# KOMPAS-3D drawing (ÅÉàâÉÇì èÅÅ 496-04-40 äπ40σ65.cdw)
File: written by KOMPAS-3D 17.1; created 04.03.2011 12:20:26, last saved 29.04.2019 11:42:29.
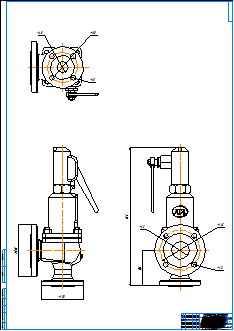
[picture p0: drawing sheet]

Sheet 1: A0, portrait

Title block, sheet 1: name: Прегран Ду 40х65; material: Внимание! Данный продукт является объектом авторского права ООО «Торговый Дом АДЛ». / Запрещается изменение, копирование, распространение / (в том числе путем копирования на другие сайты и ресурсы в Интернете) / или любое иное использование информации и объектов без предварительного / согласия правообладателя (ООО «Торговый Дом АДЛ»).; scale: 1:1; sheets: 1; organisation: ООО "Торговый дом АДЛ"; sheet format: A0; stored path: C:\Users\tra\Desktop\2д чертежи\Предохранительные клапаны ПРЕГРАН\ПРЕГРАН 496\ПРЕГРАН КПП 496-04-40\KOMPAS 2D\Прегран Ду 40х65.cdw

Views: Спереди 1, Проекционный вид 2, Проекционный вид 3
Dimensions and other numbers on the sheet: 185; 150; 130; 500; 145; 18; 65; 40; 110; 1:1; 1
